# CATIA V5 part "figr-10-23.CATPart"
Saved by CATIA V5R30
Part number: Part1
Bounding box of the stored display mesh (mm): x -174.518 to 0, y -36.805 to 36.805, z 0 to 36.805
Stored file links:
  D:\PROJECTS\CATIA V56R 2020\Resources\Parts File\c10_catia_v5_6r2020_prt\figr-10-23.CATPart
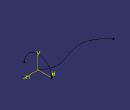
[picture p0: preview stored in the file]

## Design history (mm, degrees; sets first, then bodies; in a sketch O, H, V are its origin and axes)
Body1 (main body)
  Sketch1 on xy-plane, origin (0, 0, 0), H (1, 0, 0), V (0, 1, 0)
    spline S1 through (0, 0) (-31.5913, 14.7273) (-94.8038, 0) (-174.5181, 29.5113)
    point P1 (0, 0)
    point P2 (-94.8038, 0)
    coincidence: P1 O, P2 H
  Sketch2 on yz-plane, origin (0, 0, 0), H (0, 1, 0), V (0, 0, 1)
    arc A1 centre (0, 0) radius 36.8048 from (36.8048, 0) to (-36.8048, 0) ccw
    point P1 (-36.8048, 0)
    point P2 (36.8048, 0)
    coincidence: P1 H, P2 H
